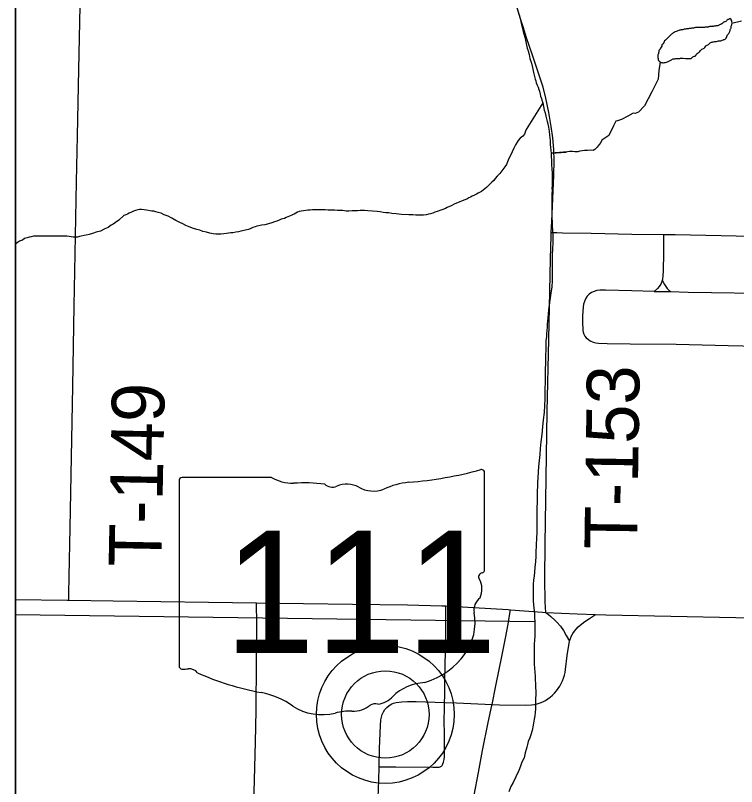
# Model space of a CAD drawing. Extents: x -483 to 680, y 0 to 440.
# Drawn here: x 45.61 to 84.51, y 68.52 to 110.14 of the extents above; entities that cross this region are included whole.
import ezdxf

# ---------------------------------------------------------------- set-up
doc = ezdxf.new("R2010")
doc.units = 0
for name, color, linetype in [('GM_X_County_Road', 7, 'Continuous'), ('GM_X_Minor_Lake', 7, 'Continuous'), ('GM_X_Minor_River', 7, 'Continuous'), ('GM_X_State_Route', 7, 'Continuous'), ('GM_X_State_Shield', 7, 'Continuous'), ('GM_X_Township_Road', 7, 'Continuous'), ('GM_X_Township_Road_Text', 7, 'Continuous'), ('GM_X_Unincorporated', 7, 'Continuous'), ('GM_X_Unincorporated_Location', 7, 'Continuous'), ('SH_Cut_Line', 7, 'Continuous'), ('SH_Text', 7, 'Continuous')]:
    doc.layers.add(name, color=color, linetype=linetype)

msp = doc.modelspace()

# ---------------------------------------------------------------- linework, layer by layer
at = {"layer": 'GM_X_County_Road'}
for points in [[(74.215, 77.92), (74.369, 77.803), (74.497, 77.702), (74.711, 77.501), (74.816, 77.399), (75.007, 77.178), (75.173, 76.937), (75.313, 76.68), (75.495, 76.366)], [(75.495, 76.366), (75.544, 76.509), (75.607, 76.646), (75.684, 76.777), (75.771, 76.901), (75.866, 77.02), (75.97, 77.131), (76.08, 77.237), (76.319, 77.427), (76.578, 77.591), (76.908, 77.799)], [(71.326, 72.954), (71.729, 72.937), (73.129, 72.909), (73.444, 72.924), (73.602, 72.947), (73.757, 72.983), (73.908, 73.033), (74.055, 73.095), (74.196, 73.168), (74.331, 73.252), (74.46, 73.346), (74.58, 73.45), (74.692, 73.563), (74.795, 73.684), (74.889, 73.811), (74.975, 73.945), (75.052, 74.084), (75.119, 74.227), (75.177, 74.374), (75.224, 74.527), (75.258, 74.682), (75.281, 74.838), (75.373, 75.592), (75.495, 76.366)], [(65.233, 69.579), (65.254, 70.574), (65.296, 71.815), (65.322, 72.119), (65.352, 72.266), (65.399, 72.408), (65.463, 72.544), (65.542, 72.67), (65.638, 72.783), (65.749, 72.882), (65.874, 72.962), (66.008, 73.02), (66.154, 73.056), (66.456, 73.099), (66.763, 73.117), (67.226, 73.116), (68.76, 73.058)], [(68.76, 73.058), (69.4, 73.033), (71.326, 72.954)], [(65.15, 66.289), (65.164, 67.308), (65.18, 67.933), (65.218, 68.864), (65.233, 69.579)]]:
    msp.add_lwpolyline(points, dxfattribs=at)
at = {"layer": 'GM_X_Minor_Lake'}
msp.add_line((83.944, 108.911), (84.028, 109.089), dxfattribs=at)
for points in [[(84.028, 109.089), (84.133, 109.239), (84.154, 109.295), (84.174, 109.352), (84.176, 109.409), (84.215, 109.465), (84.217, 109.522), (84.238, 109.597), (84.258, 109.654), (84.262, 109.787), (84.227, 109.902), (84.19, 109.96), (84.133, 109.961), (84.075, 109.925), (84.018, 109.907), (83.959, 109.852), (83.882, 109.797), (83.824, 109.78), (83.766, 109.724), (83.65, 109.651)], [(83.36, 109.564), (83.306, 109.566), (83.248, 109.548), (83.191, 109.55), (83.115, 109.533), (83.058, 109.534), (83, 109.517), (82.943, 109.499), (82.81, 109.503), (82.752, 109.486), (82.467, 109.494), (82.353, 109.478), (82.296, 109.479), (82.238, 109.462), (82.143, 109.445), (82.086, 109.447), (82.009, 109.43), (81.953, 109.432), (81.895, 109.414), (81.838, 109.416), (81.781, 109.398), (81.686, 109.401), (81.609, 109.365), (81.552, 109.367), (81.475, 109.35), (81.303, 109.297), (81.11, 109.207), (81.033, 109.153), (80.916, 109.042), (80.858, 108.986), (80.78, 108.912), (80.721, 108.838), (80.624, 108.765), (80.543, 108.596), (80.485, 108.559), (80.483, 108.483), (80.405, 108.371), (80.384, 108.315), (80.325, 108.24), (80.324, 108.183), (80.303, 108.127), (80.302, 108.07), (80.262, 108.014), (80.261, 107.957), (80.259, 107.881), (80.276, 107.824), (80.275, 107.767), (80.329, 107.67), (80.385, 107.63), (80.498, 107.589), (80.574, 107.587), (80.67, 107.604), (80.785, 107.639), (80.92, 107.711), (80.997, 107.747), (81.055, 107.783), (81.131, 107.8), (81.188, 107.799), (81.265, 107.815), (81.397, 107.812), (81.493, 107.828), (82.025, 107.814), (82.082, 107.831), (82.218, 107.941), (82.275, 107.94), (82.335, 108.033), (82.432, 108.126), (82.49, 108.162), (82.646, 108.31), (82.8, 108.401), (82.86, 108.513), (82.918, 108.531), (83.053, 108.622), (83.131, 108.677), (83.188, 108.694), (83.36, 108.728), (83.436, 108.726), (83.532, 108.761), (83.665, 108.776), (83.8, 108.83), (83.857, 108.847), (83.915, 108.884), (83.944, 108.911)], [(83.65, 109.651), (83.592, 109.634), (83.534, 109.597), (83.477, 109.58), (83.42, 109.581), (83.363, 109.564), (83.36, 109.564)]]:
    msp.add_spline(points, degree=3, dxfattribs=at)
at = {"layer": 'GM_X_Minor_River'}
for p, q in [((84.776, 109.82), (84.259, 109.706)), ((45.608, 77.811), (73.61, 77.428))]:
    msp.add_line(p, q, dxfattribs=at)
for points in [[(72.779, 110.18), (72.836, 109.971), (72.893, 109.723), (72.949, 109.495), (73.006, 109.267), (73.081, 108.963), (73.138, 108.715), (73.176, 108.525), (73.213, 108.373), (73.27, 108.221), (73.327, 108.03), (73.364, 107.821), (73.44, 107.555), (73.497, 107.327)], [(80.385, 107.63), (80.361, 107.382), (80.341, 107.287), (80.322, 107.173), (80.283, 106.698), (79.94, 106.015), (79.539, 105.256), (79.215, 104.915), (79.044, 104.839), (78.93, 104.859), (78.644, 104.707), (78.302, 104.518), (78.092, 104.443), (77.997, 104.424), (77.864, 104.177), (77.616, 103.665), (77.235, 103.4), (77.197, 103.286), (77.101, 103.172), (76.987, 103.02), (76.873, 102.907), (76.777, 102.85), (76.626, 102.87), (76.473, 102.851), (76.302, 102.851), (76.188, 102.833), (76.055, 102.814), (75.941, 102.776), (75.789, 102.777), (75.656, 102.796), (75.504, 102.797), (75.389, 102.778), (74.515, 102.705), (75.313, 102.759)], [(73.497, 107.327), (73.553, 107.06), (73.61, 106.851), (73.648, 106.699), (73.685, 106.604), (73.704, 106.509), (73.761, 106.375), (73.799, 106.261), (73.837, 106.147), (73.875, 106.052), (73.912, 105.881), (73.931, 105.786), (73.988, 105.652), (74.007, 105.557), (74.063, 105.424), (74.139, 105.025), (74.177, 104.873), (74.214, 104.701), (74.252, 104.549), (74.29, 104.416), (74.327, 104.283), (74.365, 104.112), (74.403, 103.883), (74.421, 103.674), (74.459, 103.389), (74.459, 103.161), (74.477, 103.028), (74.496, 102.857), (74.515, 102.705), (74.514, 102.533), (74.533, 102.305), (74.533, 102.153), (74.532, 102.02), (74.551, 101.906), (74.551, 101.811), (74.57, 101.678), (74.57, 101.526), (74.569, 101.374), (74.569, 101.222), (74.569, 101.07), (74.568, 100.937), (74.549, 100.823), (74.568, 100.671), (74.549, 100.519), (74.548, 100.347), (74.548, 100.119), (74.547, 99.948), (74.547, 99.701), (74.547, 99.454), (74.546, 99.226), (74.565, 98.979), (74.564, 98.77), (74.583, 98.523), (74.601, 98.313), (74.601, 98.104), (74.601, 97.857), (74.581, 97.534), (74.561, 97.23), (74.561, 96.926), (74.56, 96.622), (74.56, 96.375), (74.559, 96.052), (74.559, 95.805), (74.539, 95.482), (74.5, 95.14), (74.365, 94.247), (74.346, 94.038), (74.327, 93.81), (74.307, 93.639), (74.288, 93.486), (74.288, 93.315), (74.268, 93.125), (74.249, 92.954), (74.249, 92.783), (74.229, 92.593), (74.229, 92.384), (74.228, 92.175), (74.228, 92.042), (74.209, 91.852), (74.208, 91.586), (74.208, 91.32), (74.188, 91.073), (74.188, 90.788), (74.187, 90.56), (74.187, 90.332), (74.167, 90.009), (74.167, 89.704), (74.166, 89.419), (74.146, 89.077), (74.127, 88.716), (74.069, 88.317), (74.049, 87.937), (74.01, 87.519), (73.952, 87.12), (73.914, 86.759), (73.894, 86.436), (73.855, 86.113), (73.817, 85.79), (73.816, 85.486), (73.797, 85.182), (73.777, 84.916)], [(74.063, 105.424), (73.167, 103.982), (73.129, 103.887), (73.072, 103.735), (72.976, 103.621), (72.843, 103.508), (72.729, 103.394), (72.671, 103.299), (72.576, 103.147), (72.5, 102.977), (72.404, 102.768), (72.309, 102.578), (72.252, 102.445), (72.194, 102.331), (72.156, 102.236), (72.099, 102.084), (72.004, 101.971), (71.737, 101.61), (71.603, 101.459), (71.489, 101.345), (71.413, 101.231), (71.317, 101.136), (71.222, 101.042), (71.127, 100.966), (71.013, 100.852), (70.841, 100.701), (70.746, 100.644), (70.575, 100.549), (70.48, 100.492), (70.365, 100.436), (70.251, 100.379), (70.156, 100.322), (70.061, 100.285), (69.966, 100.228), (69.795, 100.171), (69.452, 100.02), (69.319, 99.964), (69.11, 99.869), (68.9, 99.775), (68.805, 99.718), (68.672, 99.661), (68.558, 99.624), (68.367, 99.548), (68.234, 99.511), (68.12, 99.473), (68.006, 99.435), (67.892, 99.417), (67.759, 99.379), (67.626, 99.36), (67.473, 99.361), (67.34, 99.361), (67.207, 99.362), (67.055, 99.381), (66.827, 99.382), (66.428, 99.402), (66.143, 99.422), (65.914, 99.441), (65.743, 99.48), (65.591, 99.48), (65.439, 99.5), (65.287, 99.538), (65.116, 99.558), (64.622, 99.597), (64.432, 99.617), (64.318, 99.617), (64.204, 99.617), (64.07, 99.599), (63.918, 99.599), (63.766, 99.6), (63.595, 99.581), (63.443, 99.582), (63.272, 99.601), (63.139, 99.601), (62.987, 99.602), (62.816, 99.621), (62.626, 99.622), (62.473, 99.622), (62.321, 99.642), (62.169, 99.642), (62.017, 99.643), (61.865, 99.643), (61.732, 99.644), (61.637, 99.644), (61.504, 99.625), (61.39, 99.626), (61.276, 99.607), (61.142, 99.588), (61.028, 99.57), (60.914, 99.551), (60.819, 99.513), (60.648, 99.419), (60.553, 99.381), (60.4, 99.305), (60.305, 99.268), (60.21, 99.23), (60.115, 99.173), (59.944, 99.136), (59.83, 99.079), (59.715, 99.041)], [(59.715, 99.041), (59.582, 99.003), (59.449, 98.947), (59.259, 98.89), (59.068, 98.834), (58.878, 98.815), (58.745, 98.778), (58.631, 98.759), (58.536, 98.721), (58.422, 98.684), (58.308, 98.646), (58.174, 98.589), (57.775, 98.496), (57.642, 98.458), (57.49, 98.439), (57.338, 98.402), (57.223, 98.402), (57.109, 98.383), (56.995, 98.365), (56.843, 98.346), (56.691, 98.328), (56.558, 98.328), (56.425, 98.328), (56.273, 98.348), (56.102, 98.386), (55.912, 98.444), (55.722, 98.482), (55.551, 98.54), (55.399, 98.578), (55.208, 98.636), (54.98, 98.732), (54.809, 98.808), (54.638, 98.885), (54.449, 98.98), (54.259, 99.076), (54.05, 99.191), (53.841, 99.305), (53.632, 99.382), (53.461, 99.458), (53.309, 99.497), (53.176, 99.535), (53.081, 99.574), (52.967, 99.574), (52.872, 99.593), (52.682, 99.632), (52.549, 99.651), (52.415, 99.67), (52.301, 99.671), (52.206, 99.652), (52.092, 99.614), (51.978, 99.577), (51.864, 99.52), (51.75, 99.463), (51.654, 99.407), (51.559, 99.369), (51.464, 99.331), (51.178, 99.085), (51.007, 98.971), (50.874, 98.877), (50.779, 98.82), (50.607, 98.687), (50.436, 98.612), (50.189, 98.498), (49.96, 98.442), (49.77, 98.367), (49.58, 98.31), (49.428, 98.272), (49.314, 98.254), (49.161, 98.216), (49.066, 98.198), (48.952, 98.179), (48.838, 98.179), (48.724, 98.179), (48.61, 98.18), (48.515, 98.199), (48.382, 98.219), (48.192, 98.219), (48.04, 98.219), (47.868, 98.22), (47.754, 98.22), (47.621, 98.221), (47.488, 98.221), (47.336, 98.221), (47.222, 98.222), (47.089, 98.222), (46.937, 98.223), (46.804, 98.223), (46.671, 98.223), (46.576, 98.224), (46.461, 98.186), (46.347, 98.167), (46.233, 98.13), (46.1, 98.092), (45.986, 98.016), (45.834, 97.96), (45.719, 97.884), (45.608, 97.792)], [(73.777, 84.916), (73.777, 84.688), (73.757, 84.498), (73.757, 84.27), (73.756, 84.042), (73.756, 83.794), (73.737, 83.642), (73.736, 83.433), (73.736, 83.262), (73.736, 83.129), (73.735, 82.92), (73.735, 82.711), (73.734, 82.464), (73.734, 82.217), (73.714, 81.951), (73.675, 81.153), (73.674, 80.944), (73.655, 80.659), (73.635, 80.336), (73.616, 80.108), (73.596, 79.88), (73.558, 79.671), (73.538, 79.424), (73.538, 79.177), (73.537, 79.024), (73.537, 78.815), (73.536, 78.549), (73.555, 78.34), (73.574, 78.15), (73.592, 78.017), (73.611, 77.884), (73.611, 77.732), (73.611, 77.58), (73.629, 77.466), (73.629, 77.333), (73.629, 77.181), (73.629, 77.01), (73.628, 76.858), (73.628, 76.648), (73.608, 76.42), (73.589, 76.211), (73.588, 76.021), (73.588, 75.812), (73.588, 75.603), (73.587, 75.356), (73.587, 75.128), (73.605, 74.9), (73.624, 74.691), (73.642, 74.482), (73.642, 74.273), (73.661, 74.063), (73.66, 73.854), (73.679, 73.683), (73.679, 73.474), (73.659, 73.265), (73.659, 73.075), (73.658, 72.904), (73.658, 72.714), (73.639, 72.524), (73.619, 72.334), (73.6, 72.163), (73.542, 71.84), (73.484, 71.536), (73.408, 71.308), (73.351, 71.156), (73.274, 70.948), (73.236, 70.796), (73.198, 70.644), (73.159, 70.511), (73.102, 70.34), (73.044, 70.074), (72.93, 69.827), (72.853, 69.619), (72.758, 69.391), (72.605, 69.049), (72.452, 68.745), (72.338, 68.518), (72.223, 68.233)]]:
    msp.add_lwpolyline(points, dxfattribs=at)
at = {"layer": 'GM_X_State_Route'}
for points in [[(45.608, 78.616), (48.398, 78.571), (48.489, 78.57)], [(48.489, 78.57), (50.886, 78.535), (56.018, 78.467), (58.614, 78.431)], [(58.614, 78.431), (61.15, 78.396), (63.795, 78.371), (66.75, 78.331), (68.617, 78.281), (68.82, 78.27)], [(68.82, 78.27), (70.326, 78.19), (72.189, 78.067), (72.311, 78.058)], [(72.311, 78.058), (74.05, 77.934), (74.215, 77.92)], [(74.215, 77.92), (75.913, 77.833), (76.908, 77.799)], [(76.908, 77.799), (77.467, 77.78), (84.464, 77.639), (86.797, 77.591), (88.973, 77.541), (91.462, 77.516), (95.786, 77.431)]]:
    msp.add_lwpolyline(points, dxfattribs=at)
at = {"layer": 'GM_X_State_Shield'}
for p, q in [((70.921, 80.221), (70.921, 85.455)), ((54.442, 85.035), (54.442, 75.029)), ((59.43, 85.207), (54.604, 85.207)), ((70.919, 80.222), (70.921, 80.221))]:
    msp.add_line(p, q, dxfattribs=at)
for centre, major_axis, start_param, end_param in [((65.051, 98.849), (17.476, 0), 4.814394, 5.042369), ((70.738, 85.477), (0.183, 0), 6.141152, 7.989035), ((54.63, 85.056), (0.191, 0), 1.712693, 3.28349), ((60.579, 86.369), (1.852, 0), 4.042523, 4.731795), ((61.193, 79.59), (6.648, 0), 1.404758, 1.657858), ((67.28, 82.151), (3.516, 0), 1.699011, 2.107814), ((62.702, 85.108), (0.534, 0), 3.836095, 5.185415), ((63.487, 83.952), (1.111, 0), 0.950623, 2.079405), ((64.92, 85.538), (1.336, 0), 4.081561, 5.145723), ((70.878, 79.837), (0.284, 0), 1.883978, 3.671073), ((70.725, 80.201), (0.196, 0), 5.05454, 6.418171), ((69.072, 79.175), (1.704, 0), 5.934695, 6.695948), ((71.578, 78.03), (1.24, 0), 2.387724, 3.262537), ((66.03, 77.364), (4.371, 0), 5.101752, 6.440018), ((54.632, 75.007), (0.193, 0), 3.00124, 4.508301), ((54.661, 76.031), (1.47, 0), 4.665946, 4.897461), ((54.962, 74.452), (0.53, 0), 0.519207, 1.627899), ((61.653, 83.442), (12.62, 0), 4.195997, 4.488961), ((67.873, 72.22), (2.394, 0), 1.647645, 2.488434), ((57.891, 70.534), (3.949, 0), 0.823519, 1.323587), ((64.84, 74.059), (1.412, 0), 4.937069, 5.64225), ((62.161, 74.402), (2.506, 0), 4.026481, 4.996735), ((63.792, 73.653), (1.335, 0), 4.691044, 5.507374), ((65, 72.684), (0.376, 0), 1.147584, 2.315152), ((63.609, 70.943), (2.059, 0), 1.495662, 1.94098)]:
    msp.add_ellipse(centre, major_axis=major_axis, ratio=0.8, start_param=start_param, end_param=end_param, dxfattribs=at)
at = {"layer": 'GM_X_Township_Road'}
for points in [[(48.489, 78.57), (48.495, 78.914), (48.511, 79.848), (48.566, 82.491), (48.701, 90.112), (48.776, 94.467), (48.832, 97.266), (48.903, 101.154), (48.951, 103.642), (49.026, 107.219), (49.096, 110.641)], [(74.515, 98.419), (74.546, 99.02), (74.602, 100.262), (74.647, 101.505), (74.666, 102.282), (74.648, 102.904), (74.594, 103.523), (74.512, 104.14), (74.382, 104.907), (74.223, 105.668), (74.07, 106.271), (73.888, 106.865), (73.478, 108.04), (73.181, 108.925), (72.992, 109.517), (72.853, 109.961), (72.67, 110.555)], [(74.215, 77.92), (74.182, 78.496), (74.17, 79.74), (74.19, 81.606), (74.292, 88.759), (74.377, 92.647), (74.473, 97), (74.506, 98.244), (74.515, 98.419)], [(74.515, 98.419), (74.806, 98.415), (75.118, 98.412), (76.675, 98.381), (78.855, 98.341), (80.566, 98.32)], [(80.566, 98.32), (80.566, 98.113), (80.566, 97.295), (80.547, 96.377), (80.531, 96.073), (80.512, 95.923), (80.489, 95.826)], [(80.566, 98.32), (81.191, 98.313), (83.682, 98.256), (88.51, 98.159), (90.223, 98.116), (92.247, 98.066), (92.321, 98.064), (94.426, 98.005), (95.359, 97.98), (96.137, 97.962), (97.693, 97.92), (98.627, 97.894), (99.12, 97.88)], [(80.489, 95.826), (80.477, 95.776), (80.419, 95.636), (80.336, 95.509), (80.239, 95.4), (80.058, 95.242)], [(80.489, 95.826), (80.544, 95.733), (80.615, 95.611), (80.691, 95.5), (80.77, 95.407), (80.883, 95.298), (80.944, 95.239)], [(80.058, 95.242), (78.855, 95.267), (77.445, 95.312), (77.131, 95.305), (76.975, 95.285), (76.824, 95.244), (76.682, 95.18), (76.554, 95.092), (76.446, 94.981), (76.36, 94.85), (76.3, 94.706), (76.261, 94.555), (76.237, 94.4), (76.207, 93.929), (76.205, 93.459), (76.212, 93.299), (76.22, 93.126), (76.235, 93.041), (76.266, 92.936), (76.32, 92.834), (76.393, 92.738), (76.518, 92.639), (76.62, 92.577), (76.768, 92.511), (76.917, 92.469), (77.069, 92.448), (77.534, 92.43), (78.776, 92.41), (81.26, 92.399), (82.657, 92.366), (84.052, 92.32), (85.638, 92.279)], [(80.058, 95.242), (80.82, 95.242), (80.944, 95.239)], [(80.944, 95.239), (81.908, 95.21), (83.153, 95.189), (85.627, 95.152)], [(58.449, 66.569), (58.457, 66.86), (58.508, 68.886), (58.551, 70.913), (58.59, 72.627), (58.617, 75.278), (58.625, 77.617), (58.619, 78.084), (58.614, 78.431)], [(68.76, 73.058), (68.771, 73.415), (68.774, 74.196), (68.818, 76.691), (68.828, 77.309), (68.821, 78.075), (68.82, 78.27)], [(71.326, 72.954), (71.526, 73.955), (71.868, 75.624), (71.956, 76.078), (72.048, 76.529), (72.198, 77.287), (72.265, 77.748), (72.311, 78.058)], [(68.622, 69.648), (68.648, 69.691), (68.67, 69.744), (68.703, 69.833), (68.733, 69.984), (68.747, 70.144), (68.76, 70.294), (68.754, 71.231), (68.737, 72.167), (68.746, 72.635), (68.76, 73.058)], [(70.108, 65.991), (70.103, 66.213), (70.12, 66.523), (70.162, 66.83), (70.22, 67.291), (70.361, 68.056), (70.587, 69.278), (70.805, 70.469), (71.118, 71.981), (71.313, 72.892), (71.326, 72.954)], [(65.233, 69.579), (65.523, 69.577), (66.135, 69.575), (68.125, 69.561), (68.398, 69.563), (68.432, 69.565), (68.47, 69.569), (68.516, 69.58), (68.559, 69.599), (68.591, 69.621), (68.622, 69.648)]]:
    msp.add_lwpolyline(points, dxfattribs=at)
at = {"layer": 'GM_X_Unincorporated'}
for radius in [3.72, 2.358]:
    msp.add_circle((65.563, 72.408), radius, dxfattribs=at)
at = {"layer": 'GM_X_Unincorporated_Location'}
msp.add_line((65.563, 72.408), (65.563, 72.408), dxfattribs=at)
at = {"layer": 'SH_Cut_Line'}
msp.add_lwpolyline([(45.608, 281.486), (45.608, 55.95), (373.798, 55.95)], dxfattribs=at)
at = {"layer": 'SH_Text'}
msp.add_lwpolyline([(45.608, 395.95), (385.608, 395.95), (385.608, 55.95), (45.608, 55.95)], close=True, dxfattribs=at)

# ---------------------------------------------------------------- texts
at = {"layer": 'GM_X_State_Shield'}
msp.add_text('111', height=6.5918, dxfattribs=at).set_placement((56.87, 75.735))
at = {"layer": 'GM_X_Township_Road_Text'}
for s, rotation, p in [('T-153', 89.165, (79.141, 81.313)), ('T-149', 88.8768, (53.473, 80.354))]:
    msp.add_text(s, height=2.8409, rotation=rotation, dxfattribs=at).set_placement(p)

doc.saveas('drawing.dxf')
